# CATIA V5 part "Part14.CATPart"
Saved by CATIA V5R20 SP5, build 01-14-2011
Part number: SKL_secteur_denté
Publications: "Esquisse.6", "Point.4", "Plan.1", "Droite.1", "Droite.2"
Bounding box of the stored display mesh (mm): x -20 to 20, y 0 to 60.953, z -10 to 10
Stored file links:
  F:\Catia_finish\Part14.CATPart
  F:\Catia_finish\ASS_SKL.CATProduct
  F:\Catia_finish\ASS_compresseur.CATProduct
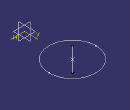
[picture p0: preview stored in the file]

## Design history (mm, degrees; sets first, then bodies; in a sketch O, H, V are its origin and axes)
External parameters (linked from other documents)
  External.rayon_secteur_dente = 20 mm
Set1
  Point1: linked copy from another document
  Plane1: linked copy from another document
Set2
  Point2: (0, 0, 0), relative to Point1
  Plane2: type Offset, RefPlane Plane1, Offset 0
  Line1: type Normal, RefPoint Point2, RefSkin Plane2, Start 10, End -10
  Line2: type Normal, RefPoint Point1, RefSkin Plane2, Start 10, End -10
Body1 (main body)
  Sketch1 on xy-plane, origin (0, 0, 0), H (1, 0, 0), V (0, 1, 0)
    circle A1 centre (0, 41) radius 20
    point P1 (0, 41)
    reference projected point E1 (0, 41) from Point1
    radius A1 = 20 {= External.rayon_secteur_dente}
    coincidence: P1 E1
